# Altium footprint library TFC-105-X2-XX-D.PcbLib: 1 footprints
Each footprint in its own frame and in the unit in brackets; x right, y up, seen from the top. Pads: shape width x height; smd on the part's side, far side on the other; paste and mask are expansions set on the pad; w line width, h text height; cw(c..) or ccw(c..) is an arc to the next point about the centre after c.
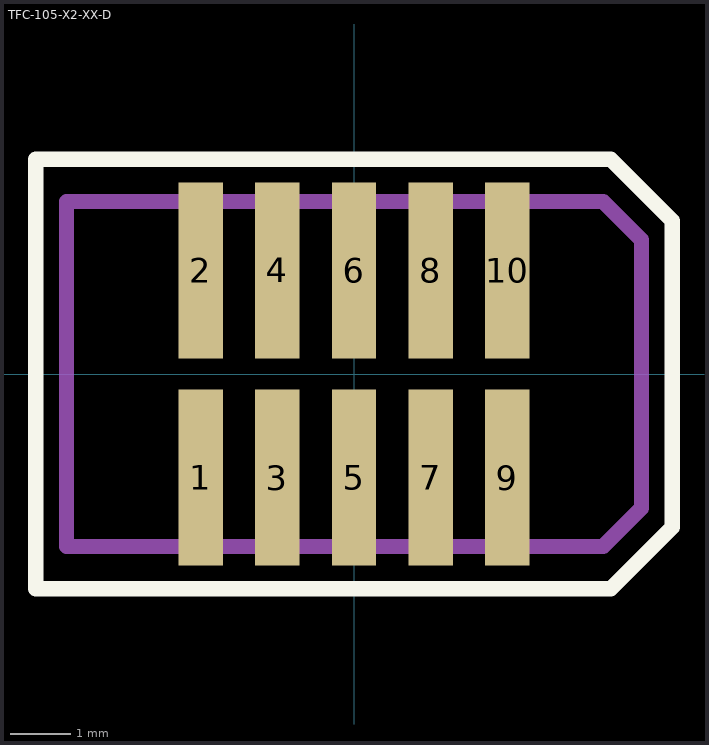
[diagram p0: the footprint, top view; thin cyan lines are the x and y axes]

## TFC-105-X2-XX-D [mil]
pads (10):
  rect 29x115 smd mask+2: 1(-100,-67.5) 2(-100,67.5) 3(-50,-67.5) 4(-50,67.5) 5(0,-67.5) 6(0,67.5) 7(50,-67.5) 8(50,67.5) 9(100,-67.5) 10(100,67.5)
Top Overlay:
  lines w10: -207.5,-140 167.5,-140 207.5,-100 207.5,100 167.5,140 -207.5,140 -207.5,-140
Mechanical 1:
  lines w10: -187.5,-112.5 162.5,-112.5 187.5,-87.5 187.5,87.5 162.5,112.5 -187.5,112.5 -187.5,-112.5
  text "J1" at -17.57,-188 h30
